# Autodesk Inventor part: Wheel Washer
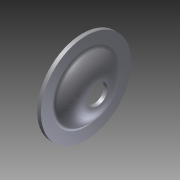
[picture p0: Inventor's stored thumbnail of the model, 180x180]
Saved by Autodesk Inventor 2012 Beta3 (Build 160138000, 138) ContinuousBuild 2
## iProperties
Created: 2010-12
Part Number: Wheel Washer
Document SubType Name: Modeling
Designer: Thom Tremblay
Density: 1 g/cm^3
Material: Default
Author: Thom Tremblay
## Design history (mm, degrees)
sketch "Sketch1"
  geometry: L1 (-1.246, 28.575)-(-1.246, 21.449); L2 (6.025, 7.188)-(6.025, 6.35); L3 (0, 0)-(18.611, 0); L4 (1.135, 28.575)-(1.135, 21.449); L5 (8.406, 7.188)-(8.406, 6.35); L6 (8.406, 6.35)-(6.025, 6.35); L7 (-1.246, 28.575)-(1.135, 28.575); A1 r 4.921 centre (3.675, 21.449) between (-1.246, 21.449) and (0.785, 17.467); A2 r 12.7 centre (-6.675, 7.188) between (6.025, 7.188) and (0.785, 17.467); A3 r 2.54 centre (3.675, 21.449) between (1.135, 21.449) and (2.183, 19.394); A4 r 15.081 centre (-6.675, 7.188) between (8.406, 7.188) and (2.183, 19.394)
  constraints: 14 end point, 8 point on circle, 5 tangent, 4 centre point, 3 parallel, 2 perpendicular, 1 vertical, 2 other
  dimensions: "d0" = 2.38125 distance between parallel lines of L4 L1; "d1" = 57.15 diameter of L1.start L3; "d2" = 12.7 diameter of L5.end L3; "d3" = 9.652 distance between parallel lines of L1 L5; "d4" = 12.7 radius of A2; "d5" = 2.54 radius of A3
revolve "Revolution1" sketch "Sketch1" stored, may be unused: angle "d6" = 90 deg
body "Solid1"
